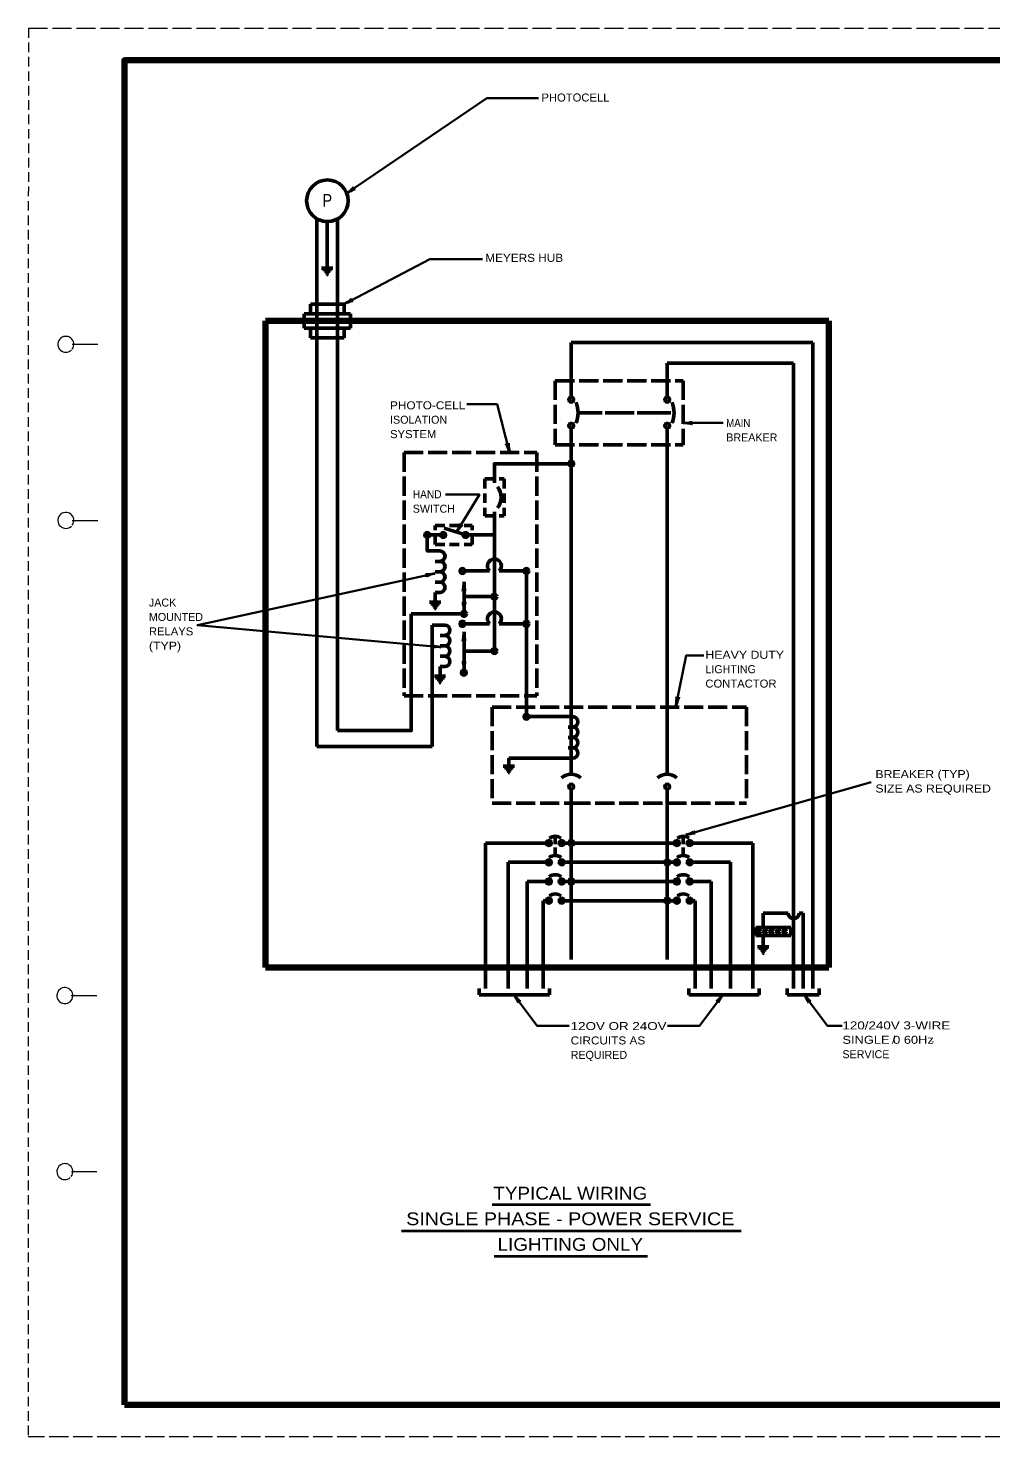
# Model space of a CAD drawing. Extents: x -1 to 679, y 0 to 440.
# Drawn here: x -1.5 to 299.3, y -0.4 to 439.6 of the extents above; entities that cross this region are included whole.
import ezdxf
from ezdxf.enums import TextEntityAlignment as Align

# ---------------------------------------------------------------- set-up
doc = ezdxf.new("R2010")
doc.units = 0
doc.linetypes.add('LONG_DASHED', pattern=[7.5, 6, -1.5])
doc.linetypes.add('MEDIUM_DASHED', pattern=[4.5, 3, -1.5])
doc.layers.add('1', color=7, linetype='Continuous', lineweight=53)
doc.layers.add('61', color=7, linetype='Continuous', lineweight=35)

msp = doc.modelspace()

# ---------------------------------------------------------------- hatches: boundary and pattern name
at = {"layer": '1'}
for points in [[(168.959, 303.557, 1), (167.459, 303.557, 1)], [(123.959, 281.307, 1), (122.459, 281.307, 1)], [(128.959, 281.307, 1), (127.459, 281.307, 1)], [(135.959, 281.307, 1), (134.459, 281.307, 1)], [(134.959, 270.057, 1), (133.459, 270.057, 1)], [(154.959, 270.057, 1), (153.459, 270.057, 1)], [(144.959, 262.057, 1), (143.459, 262.057, 1)], [(135.459, 256.682, 1), (133.959, 256.682, 1)], [(134.959, 253.557, 1), (133.459, 253.557, 1)], [(154.959, 253.557, 1), (153.459, 253.557, 1)], [(144.959, 245.057, 1), (143.459, 245.057, 1)], [(135.39, 238.286, 1), (133.89, 238.286, 1)], [(154.959, 224.557, 1), (153.459, 224.557, 1)], [(161.959, 185.057, 1), (160.459, 185.057, 1)], [(165.959, 185.057, 1), (164.459, 185.057, 1)], [(168.959, 185.057, 1), (167.459, 185.057, 1)], [(201.959, 185.057, 1), (200.459, 185.057, 1)], [(205.959, 185.057, 1), (204.459, 185.057, 1)], [(161.959, 179.057, 1), (160.459, 179.057, 1)], [(165.959, 179.057, 1), (164.459, 179.057, 1)], [(198.959, 179.057, 1), (197.459, 179.057, 1)], [(201.959, 179.057, 1), (200.459, 179.057, 1)], [(205.959, 179.057, 1), (204.459, 179.057, 1)], [(161.959, 173.057, 1), (160.459, 173.057, 1)], [(165.959, 173.057, 1), (164.459, 173.057, 1)], [(168.959, 173.057, 1), (167.459, 173.057, 1)], [(201.959, 173.057, 1), (200.459, 173.057, 1)], [(205.959, 173.057, 1), (204.459, 173.057, 1)], [(161.959, 167.057, 1), (160.459, 167.057, 1)], [(165.959, 167.057, 1), (164.459, 167.057, 1)], [(198.959, 167.057, 1), (197.459, 167.057, 1)], [(201.959, 167.057, 1), (200.459, 167.057, 1)], [(205.959, 167.057, 1), (204.459, 167.057, 1)], [(227.369, 157.432, 1), (226.369, 157.432, 1)], [(229.369, 157.432, 1), (228.369, 157.432, 1)], [(231.369, 157.432, 1), (230.369, 157.432, 1)], [(233.369, 157.432, 1), (232.369, 157.432, 1)], [(235.369, 157.432, 1), (234.369, 157.432, 1)]]:
    msp.add_hatch(color=256, dxfattribs=at).paths.add_polyline_path(points)

# ---------------------------------------------------------------- linework, layer by layer
at = {"layer": '1', "linetype": 'MEDIUM_DASHED', "lineweight": 13}
msp.add_line((-1.43, 439.624), (-1.49, -0.416), dxfattribs=at)
at = {"layer": '1'}
for p, q in [((88.709, 380.102), (88.709, 215.182)), ((91.959, 364.698), (91.959, 379.198)), ((95.209, 380.037), (95.209, 220.182)), ((90.209, 364.698), (93.709, 364.698)), ((90.584, 364.198), (93.334, 364.198)), ((91.084, 363.698), (92.834, 363.698)), ((91.459, 363.198), (92.459, 363.198)), ((91.709, 362.698), (92.209, 362.698)), ((86.709, 353.432), (97.209, 353.432)), ((86.709, 353.432), (86.709, 350.432)), ((97.209, 353.432), (97.209, 350.432)), ((84.709, 350.432), (99.209, 350.432)), ((84.709, 350.432), (84.709, 345.932)), ((99.209, 350.432), (99.209, 345.932)), ((84.709, 345.932), (99.209, 345.932)), ((86.709, 342.932), (86.709, 345.932)), ((97.209, 342.932), (97.209, 345.932)), ((86.709, 342.932), (97.209, 342.932)), ((168.209, 341.432), (243.709, 341.432)), ((243.709, 341.432), (243.709, 139.682)), ((198.209, 334.932), (237.709, 334.932)), ((198.209, 324.307), (198.209, 334.932)), ((237.709, 334.932), (237.709, 139.682)), ((170.331, 319.495), (177.831, 319.495)), ((178.831, 319.495), (187.831, 319.495)), ((188.831, 319.495), (199.331, 319.495)), ((168.209, 314.682), (168.209, 206.557)), ((198.209, 314.682), (198.209, 206.557)), ((144.209, 262.057), (144.209, 288.557)), ((135.209, 281.307), (128.552, 283.47)), ((128.209, 281.307), (123.209, 281.307)), ((144.209, 281.307), (135.209, 281.307)), ((125.709, 273.057), (127.209, 273.057)), ((125.709, 269.807), (127.209, 269.807)), ((142.709, 270.057), (134.209, 270.057)), ((125.709, 266.557), (127.209, 266.557)), ((134.709, 257.432), (134.709, 266.682)), ((123.959, 260.307), (127.459, 260.307)), ((124.334, 259.807), (127.084, 259.807)), ((125.709, 263.307), (127.209, 263.307)), ((125.709, 263.307), (125.709, 260.307)), ((144.209, 262.057), (134.709, 262.057)), ((118.209, 256.682), (134.709, 256.682)), ((124.834, 259.307), (126.584, 259.307)), ((125.209, 258.807), (126.209, 258.807)), ((125.459, 258.307), (125.959, 258.307)), ((124.709, 215.182), (124.709, 253.182)), ((124.709, 253.182), (128.709, 253.182)), ((142.709, 253.557), (134.209, 253.557)), ((134.709, 239.057), (134.709, 251.057)), ((154.209, 253.557), (145.709, 253.557)), ((127.209, 249.932), (128.709, 249.932)), ((127.209, 246.682), (128.709, 246.682)), ((127.209, 243.432), (128.709, 243.432)), ((127.209, 240.182), (128.709, 240.182)), ((127.209, 240.182), (127.209, 237.182)), ((125.459, 237.182), (128.959, 237.182)), ((125.834, 236.682), (128.584, 236.682)), ((126.334, 236.182), (128.084, 236.182)), ((126.709, 235.682), (127.709, 235.682)), ((126.959, 235.182), (127.459, 235.182)), ((168.209, 224.557), (168.709, 224.557)), ((167.209, 221.307), (168.709, 221.307)), ((167.209, 218.057), (168.709, 218.057)), ((88.709, 215.182), (124.709, 215.182)), ((148.709, 211.557), (168.709, 211.557)), ((148.709, 211.557), (148.709, 209.057)), ((167.209, 214.807), (168.709, 214.807)), ((146.959, 209.057), (150.459, 209.057)), ((147.334, 208.557), (150.084, 208.557)), ((147.834, 208.057), (149.584, 208.057)), ((148.209, 207.557), (149.209, 207.557)), ((148.459, 207.057), (148.959, 207.057)), ((168.209, 201.932), (168.209, 148.682)), ((198.209, 201.932), (198.209, 148.682)), ((141.459, 185.057), (141.459, 139.682)), ((141.459, 185.057), (161.209, 185.057)), ((163.209, 186.677), (163.209, 184.677)), ((165.209, 185.057), (201.209, 185.057)), ((203.209, 186.677), (203.209, 184.677)), ((205.209, 185.057), (224.959, 185.057)), ((224.959, 185.057), (224.959, 139.682)), ((163.209, 183.677), (163.209, 181.677)), ((203.209, 183.677), (203.209, 181.677)), ((148.459, 179.057), (161.209, 179.057)), ((148.459, 179.057), (148.459, 139.682)), ((165.209, 179.057), (201.209, 179.057)), ((205.209, 179.057), (217.959, 179.057)), ((217.959, 179.057), (217.959, 139.682)), ((154.459, 173.057), (161.209, 173.057)), ((154.459, 173.057), (154.459, 139.682)), ((165.209, 173.057), (201.209, 173.057)), ((205.209, 173.057), (211.959, 173.057)), ((211.959, 173.057), (211.959, 139.682)), ((159.459, 167.057), (161.209, 167.057)), ((159.459, 167.057), (159.459, 139.682)), ((165.209, 167.057), (201.209, 167.057)), ((205.209, 167.057), (206.959, 167.057)), ((206.959, 167.057), (206.959, 139.682)), ((228.209, 163.182), (235.959, 163.182)), ((228.209, 163.182), (228.209, 158.682)), ((240.709, 163.182), (239.459, 163.182)), ((240.709, 163.182), (240.709, 139.682)), ((225.869, 158.682), (236.869, 158.682)), ((225.869, 158.682), (225.869, 156.182)), ((236.869, 158.682), (236.869, 156.182)), ((225.869, 156.182), (236.869, 156.182)), ((228.209, 156.182), (228.209, 152.682)), ((226.459, 152.682), (229.959, 152.682)), ((226.834, 152.182), (229.584, 152.182)), ((227.334, 151.682), (229.084, 151.682)), ((227.709, 151.182), (228.709, 151.182)), ((227.959, 150.682), (228.459, 150.682)), ((139.459, 137.682), (139.459, 139.682)), ((139.459, 137.682), (161.459, 137.682)), ((161.459, 137.682), (161.459, 139.682)), ((204.959, 137.682), (204.959, 139.682)), ((204.959, 137.682), (226.959, 137.682)), ((226.959, 137.682), (226.959, 139.682)), ((235.709, 137.682), (235.709, 139.682)), ((235.709, 137.682), (245.709, 137.682)), ((245.709, 137.682), (245.709, 139.682))]:
    msp.add_line(p, q, dxfattribs=at)
at = {"layer": '1', "lineweight": 140}
for p, q in [((72.709, 348.182), (72.709, 146.182)), ((72.709, 348.182), (248.709, 348.182)), ((248.709, 348.182), (248.709, 146.182)), ((72.709, 146.182), (248.709, 146.182))]:
    msp.add_line(p, q, dxfattribs=at)
at = {"layer": '1', "linetype": 'LONG_DASHED'}
for p, q in [((163.209, 329.495), (203.209, 329.495)), ((163.209, 329.495), (163.209, 309.495)), ((203.209, 329.495), (203.209, 309.495)), ((163.209, 309.495), (203.209, 309.495)), ((115.959, 307.057), (157.459, 307.057)), ((115.959, 307.057), (115.959, 231.057)), ((157.459, 307.057), (157.459, 231.057)), ((115.959, 231.057), (157.459, 231.057)), ((143.459, 227.557), (222.959, 227.557)), ((143.459, 227.557), (143.459, 197.557)), ((222.959, 227.557), (222.959, 197.557))]:
    msp.add_line(p, q, dxfattribs=at)
at = {"layer": '1', "lineweight": 35}
for p, q in [((203.209, 316.29), (215.668, 316.29)), ((204.07, 187.608), (261.904, 204.11))]:
    msp.add_line(p, q, dxfattribs=at)
at = {"layer": '1', "linetype": 'MEDIUM_DASHED'}
for p, q in [((141.209, 298.807), (147.209, 298.807)), ((141.209, 298.807), (141.209, 287.307)), ((147.209, 298.807), (147.209, 287.307)), ((141.209, 287.307), (147.209, 287.307)), ((125.709, 278.307), (125.709, 284.307)), ((125.709, 284.307), (137.209, 284.307)), ((137.209, 278.307), (137.209, 284.307)), ((125.709, 278.307), (137.209, 278.307))]:
    msp.add_line(p, q, dxfattribs=at)
at = {"layer": '1', "lineweight": 40}
for p, q in [((143.556, 72.147), (193.002, 72.147)), ((115.158, 63.952), (221.3, 63.952)), ((144.102, 56.031), (192.019, 56.031))]:
    msp.add_line(p, q, dxfattribs=at)
at = {"layer": '1', "lineweight": 35}
for points in [[(98.08, 388.039), (141.795, 417.736), (157.995, 417.736)], [(97.209, 353.432), (123.975, 367.499), (140.499, 367.499)], [(148.964, 307.057), (145.035, 322.124), (135.639, 322.124)], [(132.379, 282.226), (139.527, 293.926), (128.949, 293.926)], [(125.595, 269.294), (51.399, 253.089), (127.539, 246.283)], [(200.934, 227.845), (204.095, 243.654), (209.603, 243.654)], [(150.301, 137.684), (157.553, 127.979), (167.548, 127.979)], [(215.566, 137.684), (208.314, 127.979), (198.319, 127.979)], [(241, 137.684), (248.252, 127.979), (252.893, 127.979)]]:
    msp.add_lwpolyline(points, dxfattribs=at)
at = {"layer": '1'}
for points in [[(168.209, 324.307), (168.209, 334.932), (168.209, 341.432)], [(144.209, 297.557), (144.209, 303.557), (168.209, 303.557)], [(123.209, 281.307), (123.209, 276.307), (127.209, 276.307)], [(154.209, 253.557), (154.209, 270.057), (145.709, 270.057)], [(144.209, 262.057), (144.209, 245.057), (134.709, 245.057)], [(95.209, 220.182), (118.209, 220.182), (118.209, 256.682)], [(154.209, 253.557), (154.209, 224.557), (168.209, 224.557)]]:
    msp.add_lwpolyline(points, dxfattribs=at)
at = {"layer": '1', "linetype": 'LONG_DASHED'}
msp.add_lwpolyline([(143.459, 197.557), (168.209, 197.557), (198.209, 197.557), (222.959, 197.557)], dxfattribs=at)
at = {"layer": '1'}
for centre, radius in [((92.016, 385.698), 6.5), ((168.209, 323.557), 0.75), ((198.209, 323.557), 0.75), ((168.209, 315.432), 0.75), ((198.209, 315.432), 0.75), ((168.209, 303.557), 0.75), ((123.209, 281.307), 0.75), ((128.209, 281.307), 0.75), ((135.209, 281.307), 0.75), ((134.209, 270.057), 0.75), ((154.209, 270.057), 0.75), ((144.209, 262.057), 0.75), ((134.709, 256.682), 0.75), ((134.209, 253.557), 0.75), ((154.209, 253.557), 0.75), ((144.209, 245.057), 0.75), ((134.64, 238.286), 0.75), ((154.209, 224.557), 0.75), ((168.209, 202.682), 0.75), ((198.209, 202.682), 0.75), ((161.209, 185.057), 0.75), ((165.209, 185.057), 0.75), ((168.209, 185.057), 0.75), ((201.209, 185.057), 0.75), ((205.209, 185.057), 0.75), ((161.209, 179.057), 0.75), ((165.209, 179.057), 0.75), ((198.209, 179.057), 0.75), ((201.209, 179.057), 0.75), ((205.209, 179.057), 0.75), ((161.209, 173.057), 0.75), ((165.209, 173.057), 0.75), ((168.209, 173.057), 0.75), ((201.209, 173.057), 0.75), ((205.209, 173.057), 0.75), ((161.209, 167.057), 0.75), ((165.209, 167.057), 0.75), ((198.209, 167.057), 0.75), ((201.209, 167.057), 0.75), ((205.209, 167.057), 0.75), ((226.869, 157.432), 0.5), ((228.869, 157.432), 0.5), ((230.869, 157.432), 0.5), ((232.869, 157.432), 0.5), ((234.869, 157.432), 0.5)]:
    msp.add_circle(centre, radius, dxfattribs=at)
for centre, radius, start, end in [((161.195, 319.495), 9.136, 338.74274, 21.25726), ((191.195, 319.495), 9.136, 338.74274, 21.25726), ((140.873, 293.057), 5.419, 323.14889, 36.85111), ((127.14, 274.682), 1.627, 272.45324, 87.54675), ((127.14, 271.432), 1.627, 272.45324, 87.54675), ((144.209, 271.626), 2.17, 313.71808, 226.28192), ((127.14, 268.182), 1.627, 272.45324, 87.54675), ((127.14, 264.932), 1.627, 272.45324, 87.54675), ((144.209, 255.126), 2.17, 313.71808, 226.28192), ((128.64, 251.557), 1.627, 272.45324, 87.54675), ((128.64, 248.307), 1.627, 272.45324, 87.54675), ((128.64, 245.057), 1.627, 272.45324, 87.54675), ((128.64, 241.807), 1.627, 272.45324, 87.54675), ((168.64, 222.932), 1.627, 272.45324, 87.54675), ((168.64, 219.682), 1.627, 272.45324, 87.54675), ((168.64, 216.432), 1.627, 272.45324, 87.54675), ((168.64, 213.182), 1.627, 272.45324, 87.54675), ((168.209, 201.994), 4.562, 48.88791, 131.11209), ((198.209, 201.994), 4.562, 48.88791, 131.11209), ((163.209, 184.031), 3.146, 53.41416, 126.58584), ((203.209, 184.031), 3.146, 53.41416, 126.58584), ((163.209, 178.031), 3.146, 53.41416, 126.58584), ((203.209, 178.031), 3.146, 53.41416, 126.58584), ((163.209, 172.031), 3.146, 53.41416, 126.58584), ((203.209, 172.031), 3.146, 53.41416, 126.58584), ((163.209, 166.031), 3.146, 53.41416, 126.58584), ((203.209, 166.031), 3.146, 53.41416, 126.58584), ((237.709, 163.201), 1.75, 180.62582, 359.37418)]:
    msp.add_arc(centre, radius, start, end, dxfattribs=at)
at = {"layer": '1', "lineweight": 40}
for centre, major_axis, ratio, start_param, end_param in [((98.827, 388.88), (-1.389, -1.133), 0.122415, 0.8963533, 3.1415927), ((99.126, 388.493), (1.552, 0.842), 0.07063, 6.2823074, 8.5597026), ((98.047, 354.184), (-1.508, -0.969), 0.122415, 0.8963533, 3.1415927), ((98.047, 354.184), (-1.508, -0.969), 0.122415, 0.8963533, 3.1415927), ((98.3, 353.766), (-1.637, -0.662), 0.07063, 3.1407148, 5.41811), ((98.3, 353.766), (-1.637, -0.662), 0.07063, 3.1407148, 5.41811), ((204.33, 316.078), (-1.756, 0.176), 0.07063, 3.1407148, 5.41811), ((204.33, 316.078), (-1.756, 0.176), 0.07063, 3.1407148, 5.41811), ((204.301, 316.566), (-1.786, -0.156), 0.122415, 0.8963533, 3.1415927), ((204.301, 316.566), (-1.786, -0.156), 0.122415, 0.8963533, 3.1415927), ((148.422, 308.043), (0.602, -1.689), 0.122415, 0.8963533, 3.1415927), ((148.422, 308.043), (0.602, -1.689), 0.122415, 0.8963533, 3.1415927), ((148.886, 308.195), (0.273, -1.744), 0.07063, 3.1407148, 5.41811), ((148.886, 308.195), (0.273, -1.744), 0.07063, 3.1407148, 5.41811), ((132.713, 283.302), (-0.798, -1.605), 0.122415, 0.8963533, 3.1415927), ((132.713, 283.302), (-0.798, -1.605), 0.122415, 0.8963533, 3.1415927), ((133.144, 283.072), (1.066, 1.407), 0.07063, 6.2823074, 8.5597026), ((133.144, 283.072), (1.066, 1.407), 0.07063, 6.2823074, 8.5597026), ((124.455, 269.262), (-1.753, -0.203), 0.07063, 6.2823074, 8.5597026), ((124.455, 269.262), (-1.753, -0.203), 0.07063, 6.2823074, 8.5597026), ((124.588, 268.792), (1.711, 0.534), 0.122415, 0.8963533, 3.1415927), ((124.588, 268.792), (1.711, 0.534), 0.122415, 0.8963533, 3.1415927), ((134.498, 265.561), (0.176, 1.756), 0.07063, 3.1407148, 5.41811), ((134.986, 265.591), (-0.156, 1.786), 0.122415, 0.8963533, 3.1415927), ((134.433, 258.523), (0.156, -1.786), 0.122415, 0.8963533, 3.1415927), ((134.921, 258.553), (-0.176, -1.756), 0.07063, 3.1407148, 5.41811), ((134.498, 249.936), (0.176, 1.756), 0.07063, 3.1407148, 5.41811), ((134.986, 249.966), (-0.156, 1.786), 0.122415, 0.8963533, 3.1415927), ((126.442, 246.593), (-1.734, 0.331), 0.07063, 6.2823074, 8.5597026), ((126.442, 246.593), (-1.734, 0.331), 0.07063, 6.2823074, 8.5597026), ((126.428, 246.105), (1.793, -0.003), 0.122415, 0.8963533, 3.1415927), ((126.428, 246.105), (1.793, -0.003), 0.122415, 0.8963533, 3.1415927), ((134.433, 240.148), (0.156, -1.786), 0.122415, 0.8963533, 3.1415927), ((134.921, 240.178), (-0.176, -1.756), 0.07063, 3.1407148, 5.41811), ((200.877, 228.97), (-0.197, -1.782), 0.122415, 0.8963533, 3.1415927), ((201.361, 228.903), (0.517, 1.688), 0.07063, 6.2823074, 8.5597026), ((205.044, 188.173), (-1.674, -0.64), 0.122415, 0.8963533, 3.1415927), ((205.206, 187.712), (1.737, 0.313), 0.07063, 6.2823074, 8.5597026), ((150.802, 136.659), (0.911, -1.512), 0.07063, 6.2823074, 8.5597026), ((151.176, 136.975), (-1.194, 1.337), 0.122415, 0.8963533, 3.1415927), ((214.691, 136.975), (1.194, 1.337), 0.122415, 3.1415927, 5.386832), ((215.064, 136.659), (-0.911, -1.512), 0.07063, 4.006668, 6.2840632), ((241.501, 136.659), (0.911, -1.512), 0.07063, 6.2823074, 8.5597026), ((241.875, 136.975), (-1.194, 1.337), 0.122415, 0.8963533, 3.1415927)]:
    msp.add_ellipse(centre, major_axis=major_axis, ratio=ratio, start_param=start_param, end_param=end_param, dxfattribs=at)
at = {"layer": '61', "linetype": 'LONG_DASHED', "lineweight": 13}
for p, q in [((-1.43, 439.624), (678.59, 439.624)), ((678.57, -0.396), (-1.49, -0.416))]:
    msp.add_line(p, q, dxfattribs=at)
at = {"layer": '61', "lineweight": 13}
for p, q in [((12.29, 340.864), (20.27, 340.884)), ((12.27, 285.864), (20.27, 285.864)), ((11.99, 137.444), (19.99, 137.444)), ((12.01, 82.424), (19.99, 82.424))]:
    msp.add_line(p, q, dxfattribs=at)
at = {"layer": '61', "lineweight": 158}
msp.add_line((667.63, 9.584), (28.57, 9.604), dxfattribs=at)
msp.add_lwpolyline([(667.61, 429.624), (28.57, 429.624), (28.57, 9.604)], dxfattribs=at)
at = {"layer": '61', "lineweight": 13}
for centre, start, end in [((10.268, 340.865), 323.13009, 316.23216), ((10.268, 285.865), 323.13009, 315.37577), ((9.988, 137.425), 322.67175, 321.71615), ((9.988, 82.425), 323.13009, 312.31439)]:
    msp.add_arc(centre, 2.5, start, end, dxfattribs=at)

# ---------------------------------------------------------------- texts
at = {"layer": '1'}
for s, height, width, p in [('PHOTOCELL', 2.5, 1.05, (158.906, 416.708)), ('P', 4, 0.85, (90.441, 383.826)), ('MEYERS HUB', 2.5, 1.1, (141.365, 366.632)), ('PHOTO-CELL', 2.5, 1.1, (111.605, 320.562)), ('MAIN', 2.5, 0.9, (216.652, 315.042)), ('SYSTEM', 2.5, 1.05, (111.605, 311.562)), ('HAND', 2.5, 0.95, (118.7, 292.764)), ('RELAYS', 2.5, 1.05, (36.245, 249.943)), ('(TYP)', 2.5, 1.15, (36.245, 245.443)), ('HEAVY DUTY', 2.5, 1.15, (210.133, 242.633)), ('CONTACTOR', 2.5, 1.05, (210.133, 233.633)), ('BREAKER (TYP)', 2.5, 1.15, (263.257, 205.357)), ('SIZE AS REQUIRED', 2.5, 1.15, (263.257, 200.857)), ('12OV OR 24OV', 2.5, 1.25, (168.038, 126.655)), ('120/240V 3-WIRE', 2.5, 1.25, (252.968, 126.854)), ('CIRCUITS AS', 2.5, 1.1, (168.038, 122.155)), ('SINGLE 0 60Hz', 2.5, 1.2, (252.968, 122.354))]:
    msp.add_text(s, height=height, dxfattribs=dict(at, width=width)).set_placement(p)
for s, p in [('ISOLATION', (111.605, 316.062)), ('BREAKER', (216.652, 310.542)), ('SWITCH', (118.7, 288.264)), ('JACK', (36.245, 258.943)), ('MOUNTED', (36.245, 254.443)), ('LIGHTING', (210.133, 238.133)), ('/', (268.471, 122.369)), ('REQUIRED', (168.038, 117.655)), ('SERVICE', (252.968, 117.854)), ('-', (280.644, 121.963))]:
    msp.add_text(s, height=2.5, dxfattribs=at).set_placement(p)
for s, width, p in [('TYPICAL WIRING', 1.1, (167.921, 73.695)), ('SINGLE PHASE - POWER SERVICE', 1.15, (167.921, 65.695)), ('LIGHTING ONLY', 1.1, (167.921, 57.695))]:
    msp.add_text(s, height=4, dxfattribs=dict(at, width=width)).set_placement(p, align=Align.CENTER)

doc.saveas('drawing.dxf')
